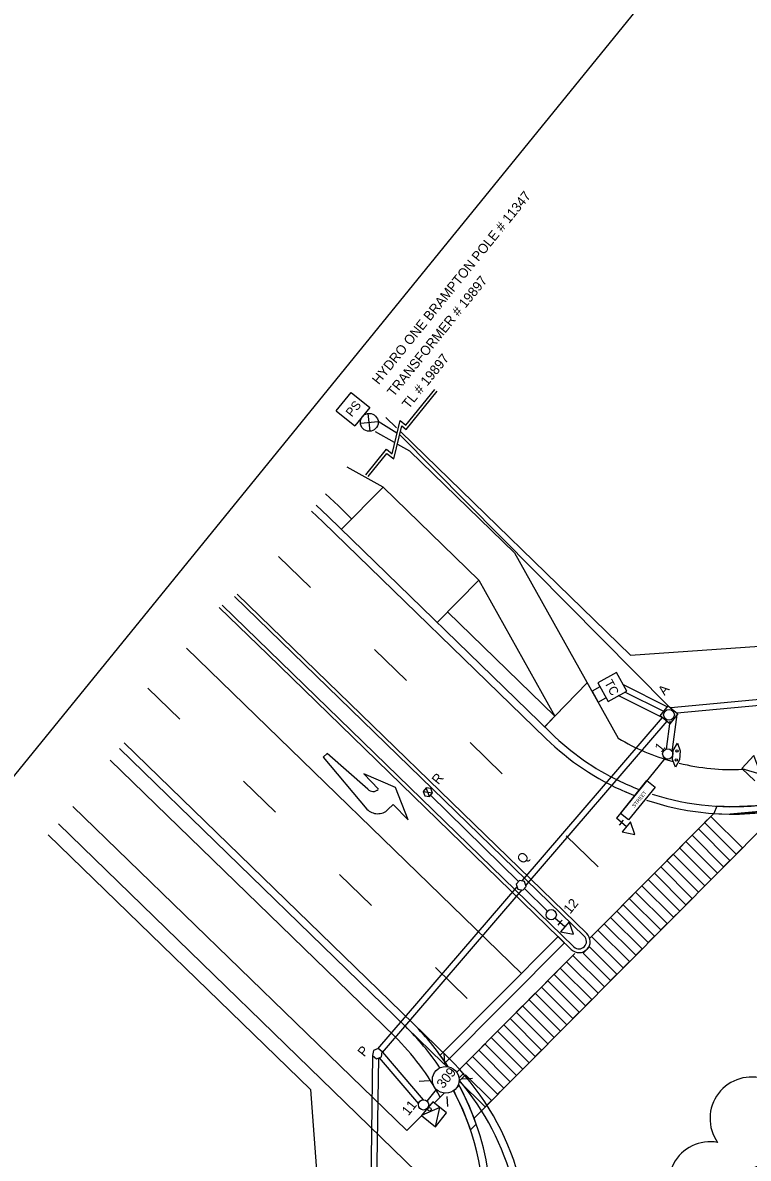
# Model space of a CAD drawing. Extents: x 592613 to 600223, y 4837996 to 4840103.
# Drawn here: x 592724.8 to 592773.7, y 4839026 to 4839102.5 of the extents above; entities that cross this region are included whole.
import ezdxf

# ---------------------------------------------------------------- set-up
doc = ezdxf.new("R2010")
doc.units = 0
for name, color, linetype in [('ENG_BORDER', 7, 'Continuous'), ('ENG_BUS-PAD', 7, 'Continuous'), ('ENG_CURB-BACK', 7, 'Continuous'), ('ENG_CURBSTOP', 7, 'Continuous'), ('ENG_EPAVT', 7, 'Continuous'), ('ENG_KILLSTRIP', 7, 'Continuous'), ('ENG_LIMITS', 7, 'Continuous'), ('ENG_MULTI-TRAIL', 7, 'Continuous'), ('ENG_SIDEWALK', 7, 'Continuous'), ('ENG_TX_TITLEBLOCK', 7, 'Continuous'), ('Level 12', 7, 'Continuous'), ('Level 58', 7, 'Continuous'), ('Level 9', 7, 'Continuous'), ('PMK_LANE', 7, 'Continuous'), ('PMK_LANE_3-6', 7, 'Continuous'), ('ROW_ENG_ROW', 7, 'Continuous'), ('TCS_100mm-NEW', 7, 'Continuous'), ('TCS_50mm-NEW', 7, 'Continuous'), ('TCS_CONTROLLER', 7, 'Continuous'), ('TCS_ELEC-CHAMBER-NEW', 7, 'Continuous'), ('TCS_LUMINAIRE-NEW', 7, 'Continuous'), ('TCS_POLE-EXIST', 7, 'Continuous'), ('TCS_POLE-NEW', 7, 'Continuous'), ('TCS_POWER', 7, 'Continuous'), ('TCS_PUSHBUTTON', 7, 'Continuous'), ('TCS_SIGN', 7, 'Continuous'), ('TCS_SIGNALHEAD', 7, 'Continuous')]:
    doc.layers.add(name, color=color, linetype=linetype)

msp = doc.modelspace()

# ---------------------------------------------------------------- linework, layer by layer
at = {"layer": 'ENG_BORDER'}
msp.add_lwpolyline([(592783.858, 4839125.156), (592658.479, 4838970.843)], dxfattribs=at)
at = {"layer": 'ENG_BUS-PAD'}
for p, q in [((592746.263, 4839068.339), (592749.079, 4839071.18)), ((592755.535, 4839064.908), (592749.079, 4839071.18)), ((592752.718, 4839062.067), (592755.535, 4839064.908))]:
    msp.add_line(p, q, dxfattribs=at)
at = {"layer": 'ENG_CURB-BACK'}
for p, q in [((592745.379, 4839069.197), (592744.578, 4839069.961)), ((592760.4, 4839054.605), (592745.379, 4839069.197)), ((592762.629, 4839040.938), (592739.072, 4839063.823)), ((592761.932, 4839040.22), (592738.238, 4839063.238)), ((592753.09, 4839032.428), (592731.33, 4839053.568))]:
    msp.add_line(p, q, dxfattribs=at)
for centre, radius, start, end in [((592772.594, 4839067.157), 17.5, 225.82889, 244.21969), ((592772.594, 4839067.157), 17.5, 252.07774, 302.49821), ((592772.594, 4839067.157), 17.5, 243.92917, 248.76974), ((592762.28, 4839040.579), 0.5, 315.82889, 45.82889), ((592762.28, 4839040.579), 0.5, 225.82889, 315.82889), ((592738.367, 4839022.332), 17.5, 33.78355, 45.82889), ((592738.367, 4839022.332), 16.5, 28.04517, 45.82899), ((592740.896, 4839019.876), 17.5, 44.53353, 45.82889), ((592740.896, 4839019.876), 17.5, 348.36992, 40.5041), ((592738.367, 4839022.332), 17.5, 322.63771, 27.91195)]:
    msp.add_arc(centre, radius, start, end, dxfattribs=at)
at = {"layer": 'ENG_CURBSTOP'}
msp.add_lwpolyline([(592754.964, 4839027.882), (592755.357, 4839028.278), (592755.092, 4839028.988), (592754.865, 4839029.532), (592754.643, 4839030.02), (592754.32, 4839030.67), (592754.207, 4839030.886), (592754.207, 4839030.886), (592753.843, 4839030.519), (592753.974, 4839030.202), (592754.452, 4839029.227), (592754.793, 4839028.37)], close=True, dxfattribs=at)
at = {"layer": 'ENG_EPAVT'}
for p, q in [((592745.032, 4839068.837), (592744.263, 4839069.571)), ((592760.051, 4839054.246), (592745.032, 4839068.837)), ((592762.803, 4839041.117), (592739.266, 4839063.982)), ((592761.758, 4839040.041), (592741.316, 4839059.9)), ((592753.438, 4839032.787), (592731.645, 4839053.958)), ((592750.682, 4839027.843), (592728.182, 4839049.672)), ((592752.53, 4839029.695), (592753.192, 4839030.359)), ((592750.682, 4839027.843), (592751.677, 4839028.841))]:
    msp.add_line(p, q, dxfattribs=at)
for centre, radius, start, end in [((592772.594, 4839067.157), 18, 251.2988, 322.63771), ((592772.594, 4839067.157), 18, 225.82889, 246.58672), ((592772.594, 4839067.157), 18, 246.15834, 248.31266), ((592762.28, 4839040.579), 0.75, 315.82889, 45.82889), ((592762.28, 4839040.579), 0.75, 225.82889, 315.82889), ((592738.367, 4839022.332), 18, 33.00677, 45.82889), ((592740.896, 4839019.876), 18, 349.34998, 45.82889), ((592738.367, 4839022.332), 18, 345.94534, 28.68873)]:
    msp.add_arc(centre, radius, start, end, dxfattribs=at)
at = {"layer": 'ENG_KILLSTRIP'}
for p, q in [((592746.073, 4839069.918), (592745.209, 4839070.742)), ((592746.967, 4839069.048), (592746.073, 4839069.918)), ((592760.654, 4839055.752), (592753.422, 4839062.778)), ((592749.865, 4839034.167), (592730.699, 4839052.787))]:
    msp.add_line(p, q, dxfattribs=at)
at = {"layer": 'ENG_LIMITS'}
msp.add_lwpolyline([(592778.119, 4839050.026), (592777.723, 4839050.427), (592777.481, 4839050.349), (592777.02, 4839050.224), (592775.671, 4839049.93), (592774.169, 4839049.721), (592773.084, 4839049.671), (592772.54, 4839049.646), (592771.553, 4839049.69), (592771.352, 4839049.2), (592771.895, 4839049.169), (592772.416, 4839049.159), (592772.909, 4839049.163), (592773.173, 4839049.165), (592773.631, 4839049.188), (592774.226, 4839049.233), (592774.825, 4839049.296), (592775.913, 4839049.465), (592772.454, 4839049.158), (592775.898, 4839049.463), (592776.144, 4839049.517), (592776.956, 4839049.693), (592777.648, 4839049.885)], close=True, dxfattribs=at)
for centre, start, end in [((592773.893, 4839028.653), 70.23304, 215.23304), ((592771.108, 4839024.295), 79.60528, 224.60528)]:
    msp.add_arc(centre, 2.793, start, end, dxfattribs=at)
at = {"layer": 'ENG_MULTI-TRAIL'}
for p, q in [((592749.846, 4839074.188), (592748.569, 4839074.9)), ((592750.886, 4839073.606), (592750.069, 4839074.063)), ((592757.939, 4839066.755), (592750.886, 4839073.606)), ((592749.079, 4839071.18), (592746.656, 4839072.533)), ((592755.535, 4839064.908), (592760.654, 4839055.752))]:
    msp.add_line(p, q, dxfattribs=at)
at = {"layer": 'ENG_SIDEWALK'}
for p, q in [((592757.939, 4839066.755), (592764.921, 4839054.268)), ((592762.835, 4839057.998), (592759.957, 4839055.035)), ((592760.654, 4839055.752), (592762.835, 4839057.998)), ((592759.965, 4839055.027), (592760.654, 4839055.752)), ((592753.347, 4839023.116), (592727.227, 4839048.491)), ((592754.195, 4839031.366), (592754.529, 4839031.703)), ((592752.569, 4839029.726), (592753.196, 4839030.358))]:
    msp.add_line(p, q, dxfattribs=at)
for start, end in [(239.23299, 254.56403), (256.23854, 272.67955)]:
    msp.add_arc((592772.594, 4839067.157), 15, start, end, dxfattribs=at)
at = {"layer": 'Level 12'}
for p, q in [((592745.311, 4839053.25), (592745.047, 4839052.997)), ((592748.048, 4839050.834), (592745.311, 4839053.25)), ((592745.047, 4839052.997), (592747.999, 4839049.492)), ((592749.92, 4839050.945), (592747.783, 4839051.875)), ((592747.783, 4839051.875), (592748.777, 4839050.84)), ((592750.764, 4839048.772), (592749.92, 4839050.945)), ((592749.413, 4839049.463), (592749.77, 4839049.806)), ((592749.77, 4839049.806), (592750.764, 4839048.772))]:
    msp.add_line(p, q, dxfattribs=at)
for centre, radius, start, end in [((592748.409, 4839051.181), 0.5, 223.81988, 313.84356), ((592748.72, 4839050.184), 1, 223.82625, 313.84843)]:
    msp.add_arc(centre, radius, start, end, dxfattribs=at)
at = {"layer": 'Level 58'}
for p, q in [((592750.612, 4839075.356), (592752.559, 4839077.765)), ((592750.642, 4839075.075), (592752.714, 4839077.639)), ((592749.684, 4839073.433), (592750.233, 4839075.663)), ((592749.804, 4839073.079), (592750.352, 4839075.309)), ((592750.233, 4839075.663), (592750.612, 4839075.356)), ((592750.352, 4839075.309), (592750.642, 4839075.075)), ((592747.918, 4839072.023), (592749.305, 4839073.739)), ((592748.074, 4839071.898), (592749.335, 4839073.458)), ((592749.305, 4839073.739), (592749.684, 4839073.433)), ((592749.335, 4839073.458), (592749.804, 4839073.079))]:
    msp.add_line(p, q, dxfattribs=at)
at = {"layer": 'Level 9'}
msp.add_lwpolyline([(592768.9, 4839053.941), (592769.097, 4839053.412), (592769.05, 4839052.808), (592768.771, 4839052.317), (592768.574, 4839052.846), (592768.622, 4839053.45)], close=True, dxfattribs=at)
for centre in [(592768.877, 4839053.409), (592768.83, 4839052.806)]:
    msp.add_circle(centre, 0.075, dxfattribs=at)
at = {"layer": 'PMK_LANE'}
for p, q in [((592738.051, 4839063.081), (592741.316, 4839059.9)), ((592758.4, 4839038.424), (592735.838, 4839060.342)), ((592775.139, 4839048.757), (592755.211, 4839028.681)), ((592771.352, 4839049.2), (592763.032, 4839040.819)), ((592771.16, 4839049.007), (592770.737, 4839048.581)), ((592770.737, 4839048.581), (592772.861, 4839046.462)), ((592773.283, 4839046.888), (592771.16, 4839049.007)), ((592770.315, 4839048.155), (592769.892, 4839047.73)), ((592772.438, 4839046.036), (592770.315, 4839048.155)), ((592769.469, 4839047.304), (592769.047, 4839046.878)), ((592771.593, 4839045.184), (592769.469, 4839047.304)), ((592769.892, 4839047.73), (592772.015, 4839045.61)), ((592768.624, 4839046.452), (592768.201, 4839046.026)), ((592770.747, 4839044.333), (592768.624, 4839046.452)), ((592769.047, 4839046.878), (592771.17, 4839044.758)), ((592772.861, 4839046.462), (592773.283, 4839046.888)), ((592767.779, 4839045.6), (592767.356, 4839045.175)), ((592769.902, 4839043.481), (592767.779, 4839045.6)), ((592768.201, 4839046.026), (592770.324, 4839043.907)), ((592772.015, 4839045.61), (592772.438, 4839046.036)), ((592766.933, 4839044.749), (592766.51, 4839044.323)), ((592769.056, 4839042.629), (592766.933, 4839044.749)), ((592767.356, 4839045.175), (592769.479, 4839043.055)), ((592771.17, 4839044.758), (592771.593, 4839045.184)), ((592766.51, 4839044.323), (592768.634, 4839042.204)), ((592770.324, 4839043.907), (592770.747, 4839044.333)), ((592765.665, 4839043.471), (592767.788, 4839041.352)), ((592768.211, 4839041.778), (592766.088, 4839043.897)), ((592769.479, 4839043.055), (592769.902, 4839043.481)), ((592765.242, 4839043.046), (592764.82, 4839042.62)), ((592764.82, 4839042.62), (592766.943, 4839040.5)), ((592767.366, 4839040.926), (592765.242, 4839043.046)), ((592768.634, 4839042.204), (592769.056, 4839042.629)), ((592764.397, 4839042.194), (592763.974, 4839041.768)), ((592763.974, 4839041.768), (592766.097, 4839039.649)), ((592766.52, 4839040.074), (592764.397, 4839042.194)), ((592767.788, 4839041.352), (592768.211, 4839041.778)), ((592760.866, 4839040.908), (592752.93, 4839032.913)), ((592763.552, 4839041.342), (592763.129, 4839040.916)), ((592763.129, 4839040.916), (592765.252, 4839038.797)), ((592765.675, 4839039.223), (592763.552, 4839041.342)), ((592766.943, 4839040.5), (592767.366, 4839040.926)), ((592761.296, 4839040.49), (592753.279, 4839032.414)), ((592762.979, 4839040.219), (592762.556, 4839039.793)), ((592764.83, 4839038.372), (592762.979, 4839040.219)), ((592761.995, 4839039.774), (592754.043, 4839031.763)), ((592761.861, 4839039.639), (592761.438, 4839039.213)), ((592763.984, 4839037.519), (592761.861, 4839039.639)), ((592762.556, 4839039.793), (592764.407, 4839037.945)), ((592766.097, 4839039.649), (592766.52, 4839040.074)), ((592761.015, 4839038.787), (592760.593, 4839038.361)), ((592763.138, 4839036.668), (592761.015, 4839038.787)), ((592761.438, 4839039.213), (592763.561, 4839037.094)), ((592765.252, 4839038.797), (592765.675, 4839039.223)), ((592760.17, 4839037.936), (592759.747, 4839037.51)), ((592762.293, 4839035.816), (592760.17, 4839037.936)), ((592760.593, 4839038.361), (592762.716, 4839036.242)), ((592764.407, 4839037.945), (592764.83, 4839038.372)), ((592759.324, 4839037.084), (592758.902, 4839036.658)), ((592761.448, 4839034.965), (592759.324, 4839037.084)), ((592759.747, 4839037.51), (592761.87, 4839035.39)), ((592763.561, 4839037.094), (592763.984, 4839037.519)), ((592758.902, 4839036.658), (592761.025, 4839034.539)), ((592762.716, 4839036.242), (592763.138, 4839036.668)), ((592758.479, 4839036.232), (592758.056, 4839035.807)), ((592758.056, 4839035.807), (592760.18, 4839033.687)), ((592760.602, 4839034.113), (592758.479, 4839036.232)), ((592761.87, 4839035.39), (592762.293, 4839035.816)), ((592757.634, 4839035.381), (592757.211, 4839034.955)), ((592757.211, 4839034.955), (592759.334, 4839032.835)), ((592759.757, 4839033.261), (592757.634, 4839035.381)), ((592761.025, 4839034.539), (592761.448, 4839034.965)), ((592756.788, 4839034.529), (592756.366, 4839034.103)), ((592756.366, 4839034.103), (592758.489, 4839031.984)), ((592758.911, 4839032.41), (592756.788, 4839034.529)), ((592760.18, 4839033.687), (592760.602, 4839034.113)), ((592755.943, 4839033.677), (592755.52, 4839033.252)), ((592755.52, 4839033.252), (592757.643, 4839031.132)), ((592758.066, 4839031.558), (592755.943, 4839033.677)), ((592759.334, 4839032.835), (592759.757, 4839033.261)), ((592755.097, 4839032.826), (592754.675, 4839032.4)), ((592757.221, 4839030.706), (592755.097, 4839032.826)), ((592754.675, 4839032.4), (592756.798, 4839030.281)), ((592758.489, 4839031.984), (592758.911, 4839032.41)), ((592754.636, 4839031.593), (592754.212, 4839031.166)), ((592754.212, 4839031.166), (592755.953, 4839029.429)), ((592756.376, 4839029.856), (592754.636, 4839031.593)), ((592757.643, 4839031.132), (592758.066, 4839031.558)), ((592756.798, 4839030.281), (592757.221, 4839030.706)), ((592755.953, 4839029.429), (592756.376, 4839029.856))]:
    msp.add_line(p, q, dxfattribs=at)
msp.add_lwpolyline([(592766.088, 4839043.897), (592765.712, 4839043.519), (592765.665, 4839043.471)], dxfattribs=at)
msp.add_lwpolyline([(592752.93, 4839032.913), (592760.866, 4839040.908), (592761.296, 4839040.49), (592753.279, 4839032.414)], close=True, dxfattribs=at)
at = {"layer": 'PMK_LANE_3-6'}
for p, q in [((592744.193, 4839064.424), (592742.041, 4839066.515)), ((592750.649, 4839058.153), (592748.497, 4839060.243)), ((592735.386, 4839055.552), (592733.234, 4839057.643)), ((592757.105, 4839051.881), (592754.953, 4839053.971)), ((592741.842, 4839049.281), (592739.69, 4839051.371)), ((592763.56, 4839045.609), (592761.408, 4839047.7)), ((592748.298, 4839043.009), (592746.146, 4839045.1)), ((592754.753, 4839036.738), (592752.602, 4839038.828))]:
    msp.add_line(p, q, dxfattribs=at)
at = {"layer": 'ROW_ENG_ROW'}
for p, q in [((592749.984, 4839075.18), (592749.26, 4839075.883)), ((592765.752, 4839059.862), (592750.271, 4839074.901)), ((592765.752, 4839059.862), (592785.547, 4839061.253)), ((592744.202, 4839030.606), (592726.538, 4839047.766)), ((592744.202, 4839030.606), (592745.857, 4839008.239))]:
    msp.add_line(p, q, dxfattribs=at)
at = {"layer": 'TCS_100mm-NEW'}
for p, q in [((592767.869, 4839055.676), (592764.906, 4839057.138)), ((592767.98, 4839056.079), (592765.374, 4839057.365)), ((592780.049, 4839057.397), (592768.465, 4839056.313)), ((592767.877, 4839055.672), (592758.42, 4839044.662)), ((592768.167, 4839053.537), (592768.426, 4839055.414)), ((592758.079, 4839044.264), (592748.696, 4839033.34)), ((592758.596, 4839044.148), (592760.163, 4839042.628)), ((592748.38, 4839032.901), (592748.111, 4839014.474)), ((592749.035, 4839033.121), (592751.771, 4839029.912))]:
    msp.add_line(p, q, dxfattribs=at)
at = {"layer": 'TCS_50mm-NEW'}
for p, q in [((592750.004, 4839074.818), (592748.749, 4839075.61)), ((592768.276, 4839056.446), (592750.228, 4839074.687)), ((592768.224, 4839056.382), (592765.276, 4839057.864)), ((592779.993, 4839056.99), (592768.886, 4839055.951)), ((592768.188, 4839055.421), (592758.695, 4839044.368)), ((592768.546, 4839053.356), (592768.891, 4839055.858)), ((592758.203, 4839044.608), (592752.287, 4839050.429)), ((592758.425, 4839044.054), (592749.018, 4839033.102)), ((592748.766, 4839032.728), (592748.515, 4839014.698)), ((592748.826, 4839032.75), (592751.472, 4839029.645))]:
    msp.add_line(p, q, dxfattribs=at)
at = {"layer": 'TCS_CONTROLLER'}
for p, q in [((592764.799, 4839058.692), (592763.537, 4839057.999)), ((592765.492, 4839057.43), (592764.799, 4839058.692)), ((592763.681, 4839057.723), (592763.155, 4839057.435)), ((592763.537, 4839057.999), (592764.23, 4839056.737)), ((592763.155, 4839057.435), (592763.559, 4839056.698)), ((592763.559, 4839056.698), (592764.085, 4839056.987)), ((592764.23, 4839056.737), (592765.492, 4839057.43))]:
    msp.add_line(p, q, dxfattribs=at)
at = {"layer": 'TCS_ELEC-CHAMBER-NEW'}
for p, q in [((592767.74, 4839055.783), (592768.276, 4839056.446)), ((592768.276, 4839056.446), (592768.939, 4839055.91)), ((592768.403, 4839055.247), (592767.74, 4839055.783)), ((592768.939, 4839055.91), (592768.403, 4839055.247)), ((592751.988, 4839050.938), (592751.788, 4839050.69)), ((592752.217, 4839050.343), (592751.988, 4839050.938)), ((592752.303, 4839050.889), (592751.988, 4839050.938)), ((592752.418, 4839050.591), (592752.303, 4839050.889)), ((592751.788, 4839050.69), (592752.418, 4839050.591)), ((592751.788, 4839050.69), (592751.902, 4839050.393)), ((592751.902, 4839050.393), (592752.217, 4839050.343)), ((592752.217, 4839050.343), (592752.418, 4839050.591)), ((592758.274, 4839044.688), (592758.045, 4839044.43)), ((592758.613, 4839044.618), (592758.274, 4839044.688)), ((592758.045, 4839044.43), (592758.154, 4839044.102)), ((592758.154, 4839044.102), (592758.492, 4839044.032)), ((592758.492, 4839044.032), (592758.722, 4839044.29)), ((592758.722, 4839044.29), (592758.613, 4839044.618)), ((592748.435, 4839033.242), (592748.38, 4839032.901)), ((592748.758, 4839033.365), (592748.435, 4839033.242)), ((592749.026, 4839033.147), (592748.758, 4839033.365)), ((592748.38, 4839032.901), (592748.648, 4839032.682)), ((592748.648, 4839032.682), (592748.971, 4839032.805)), ((592748.971, 4839032.805), (592749.026, 4839033.147))]:
    msp.add_line(p, q, dxfattribs=at)
msp.add_circle((592768.339, 4839055.846), 0.361, dxfattribs=at)
at = {"layer": 'TCS_LUMINAIRE-NEW'}
for p, q in [((592768.063, 4839052.914), (592764.798, 4839048.874)), ((592753.234, 4839032.375), (592753.194, 4839033.049)), ((592752.18, 4839031.185), (592751.506, 4839031.144)), ((592754.425, 4839031.32), (592755.099, 4839031.361)), ((592752.042, 4839029.827), (592752.672, 4839030.604)), ((592753.37, 4839030.13), (592753.411, 4839029.456))]:
    msp.add_line(p, q, dxfattribs=at)
msp.add_circle((592753.302, 4839031.252), 0.9, dxfattribs=at)
at = {"layer": 'TCS_POLE-EXIST'}
for p, q in [((592748.216, 4839074.95), (592748.089, 4839076.143)), ((592747.556, 4839075.483), (592748.749, 4839075.61))]:
    msp.add_line(p, q, dxfattribs=at)
msp.add_circle((592748.153, 4839075.547), 0.6, dxfattribs=at)
at = {"layer": 'TCS_POLE-NEW'}
for centre in [(592768.253, 4839053.207), (592760.405, 4839042.382), (592751.809, 4839029.568)]:
    msp.add_circle(centre, 0.346, dxfattribs=at)
at = {"layer": 'TCS_POWER'}
for p, q in [((592745.927, 4839076.318), (592746.931, 4839077.561)), ((592746.931, 4839077.561), (592748.188, 4839076.546)), ((592745.927, 4839076.318), (592747.184, 4839075.302)), ((592748.188, 4839076.546), (592747.184, 4839075.302))]:
    msp.add_line(p, q, dxfattribs=at)
at = {"layer": 'TCS_PUSHBUTTON'}
msp.add_circle((592752.206, 4839029.269), 0.12, dxfattribs=at)
at = {"layer": 'TCS_SIGN'}
msp.add_lwpolyline([(592765.063, 4839049.203), (592766.851, 4839051.416), (592767.399, 4839050.973), (592765.611, 4839048.761)], close=True, dxfattribs=at)
at = {"layer": 'TCS_SIGNALHEAD'}
for p, q in [((592773.238, 4839052.227), (592774.115, 4839051.408)), ((592765.466, 4839048.294), (592764.799, 4839048.873)), ((592765.133, 4839048.583), (592764.988, 4839048.417)), ((592765.133, 4839048.583), (592765.277, 4839048.75)), ((592765.755, 4839048.628), (592765.178, 4839047.961)), ((592766.044, 4839047.794), (592765.755, 4839048.628)), ((592765.178, 4839047.961), (592766.044, 4839047.794)), ((592761.321, 4839041.562), (592760.654, 4839042.141)), ((592760.987, 4839041.851), (592760.843, 4839041.685)), ((592760.987, 4839041.851), (592761.132, 4839042.018)), ((592761.61, 4839041.896), (592761.033, 4839041.229)), ((592761.899, 4839041.062), (592761.61, 4839041.896)), ((592761.033, 4839041.229), (592761.899, 4839041.062)), ((592752.427, 4839029.778), (592751.673, 4839028.844)), ((592753.36, 4839029.023), (592752.427, 4839029.778)), ((592752.606, 4839028.09), (592753.36, 4839029.023))]:
    msp.add_line(p, q, dxfattribs=at)
for points in [[(592774.057, 4839053.104), (592773.238, 4839052.227), (592774.524, 4839051.846), (592774.524, 4839051.846)], [(592765.755, 4839048.628), (592765.178, 4839047.961), (592766.044, 4839047.794), (592766.044, 4839047.794)], [(592761.61, 4839041.896), (592761.033, 4839041.229), (592761.899, 4839041.062), (592761.899, 4839041.062)], [(592751.673, 4839028.844), (592752.606, 4839028.09), (592752.894, 4839029.401), (592752.894, 4839029.401)]]:
    msp.add_lwpolyline(points, close=True, dxfattribs=at)

# ---------------------------------------------------------------- texts
at = {"layer": 'ENG_TX_TITLEBLOCK'}
for s, p in [('IS TO BE REPLACED WITH EXISTING SYMBOLOGY ', (592769.012, 4839015.586)), ('ALL DESIGN SYMBOLOGY ON THE MAIN PLAN', (592768.256, 4839016.906)), ('AS SHOWN IN THE MAIN LEGEND.', (592772.376, 4839017.477))]:
    msp.add_text(s, height=0.81055, rotation=50.90123, dxfattribs=at).set_placement(p)
at = {"layer": 'TCS_CONTROLLER'}
msp.add_text('TC', height=0.6, rotation=298.76852, dxfattribs=at).set_placement((592763.96, 4839058.011))
at = {"layer": 'TCS_ELEC-CHAMBER-NEW'}
for s, p in [('A', (592768.043, 4839057.108)), ('R', (592752.807, 4839051.1)), ('Q', (592758.531, 4839045.752)), ('P', (592747.813, 4839032.76))]:
    msp.add_text(s, height=0.65, rotation=51.05743, dxfattribs=at).set_placement(p)
at = {"layer": 'TCS_LUMINAIRE-NEW'}
msp.add_text('309', height=0.65, rotation=51.283, dxfattribs=at).set_placement((592753.133, 4839030.623))
at = {"layer": 'TCS_POLE-NEW'}
for s, p in [('1', (592767.819, 4839053.275)), ('12', (592761.674, 4839042.383)), ('11', (592750.787, 4839028.796))]:
    msp.add_text(s, height=0.65, rotation=51.05743, dxfattribs=at).set_placement(p)
at = {"layer": 'TCS_POWER'}
for s, height, p in [('HYDRO ONE BRAMPTON POLE # 11347', 0.65, (592748.788, 4839078.045)), ('TRANSFORMER # 19897', 0.65, (592749.799, 4839077.228)), ('TL # 19897', 0.65, (592750.81, 4839076.411)), ('PS', 0.6, (592746.977, 4839075.866))]:
    msp.add_text(s, height=height, rotation=51.05743, dxfattribs=at).set_placement(p)
at = {"layer": 'TCS_SIGN'}
msp.add_text('STREET', height=0.2407, rotation=51.05737, dxfattribs=at).set_placement((592766.021, 4839049.573))

doc.saveas('drawing.dxf')
